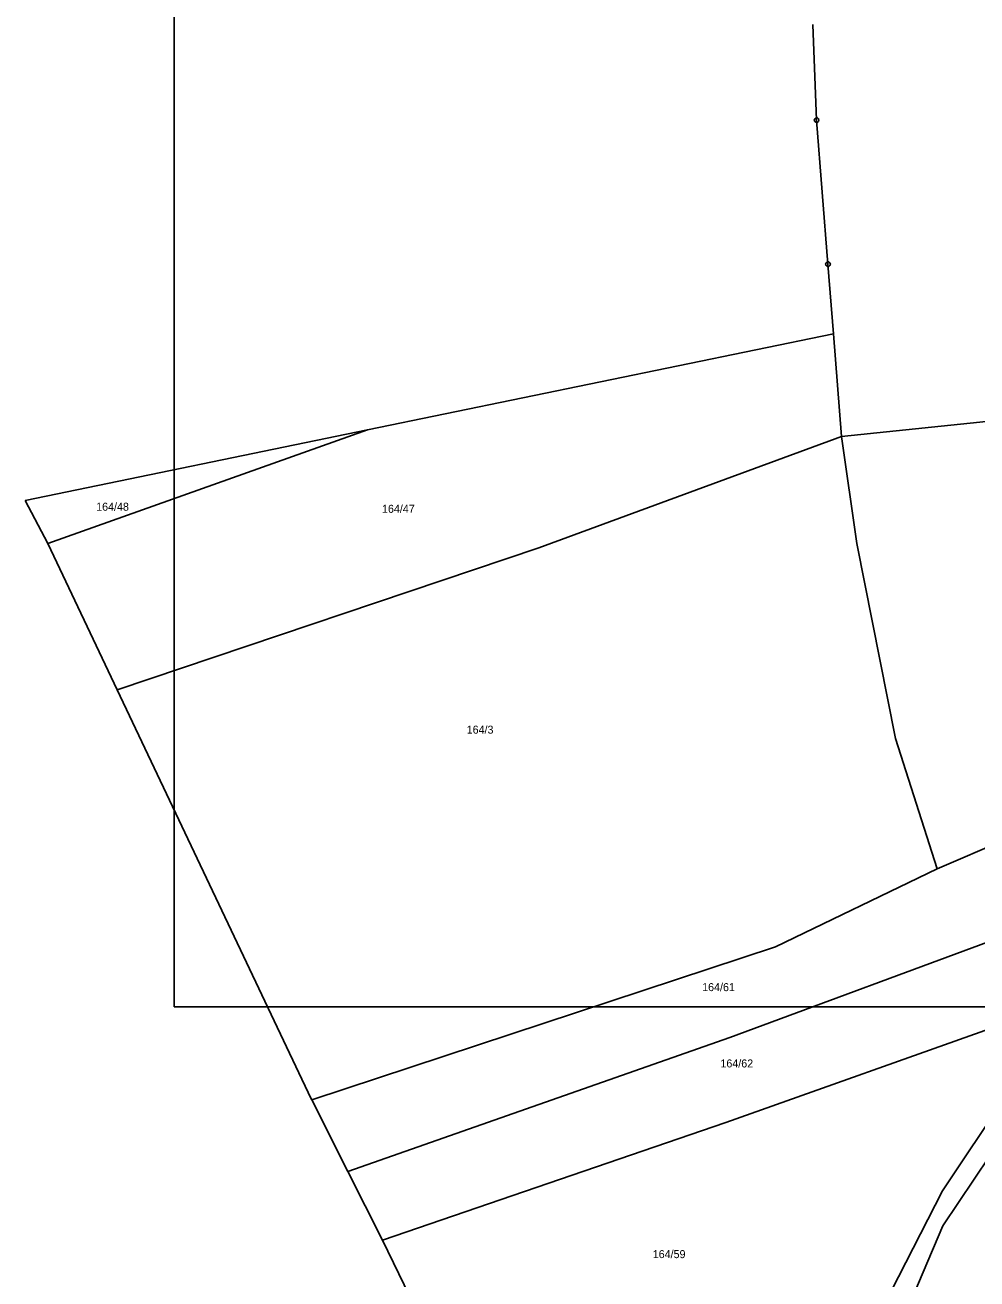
# Model space of a CAD drawing. Extents: x -779723 to -777378, y -1011169 to -1009297.
# Drawn here: x -779562.3 to -779360.2, y -1010745.7 to -1010479.3 of the extents above; entities that cross this region are included whole.
import ezdxf

# ---------------------------------------------------------------- set-up
doc = ezdxf.new("R2010")
doc.units = 0
for name, color, linetype in [('Default', 7, 'Continuous'), ('KN_HRANICE', 7, 'Continuous'), ('KN_PARCELY', 7, 'Continuous'), ('LEGENDA', 7, 'Continuous')]:
    doc.layers.add(name, color=color, linetype=linetype)

# ---------------------------------------------------------------- blocks, each defined once
blk = doc.blocks.new('105')
at = {"layer": 'Default'}
blk.add_line((-0.12, 0), (0.12, 0), dxfattribs=at)
blk.add_lwpolyline([(0.15, 0.48), (0.4, 0.3), (0.5, 0.01), (0.4, -0.28), (0.15, -0.46), (-0.16, -0.46), (-0.41, -0.28), (-0.51, 0.01), (-0.41, 0.3), (-0.16, 0.48), (0.15, 0.48)], dxfattribs=at)

msp = doc.modelspace()

# ---------------------------------------------------------------- linework, layer by layer
at = {"layer": 'KN_HRANICE'}
for p, q in [((-779394.26, -1010499.5), (-779395.1, -1010479.15)), ((-779391.85, -1010530.1), (-779394.26, -1010499.5)), ((-779390.7, -1010544.93), (-779391.85, -1010530.1)), ((-779489.63, -1010565.32), (-779390.7, -1010544.93)), ((-779389.01, -1010566.7), (-779390.7, -1010544.93)), ((-779389.01, -1010566.7), (-779301.63, -1010557.72)), ((-779562.34, -1010580.31), (-779489.63, -1010565.32)), ((-779489.63, -1010565.32), (-779557.53, -1010589.43)), ((-779389.01, -1010566.7), (-779453.28, -1010590.34)), ((-779389.01, -1010566.7), (-779385.7, -1010589.44)), ((-779557.53, -1010589.43), (-779562.34, -1010580.31)), ((-779557.53, -1010589.43), (-779542.79, -1010620.51)), ((-779453.28, -1010590.34), (-779542.79, -1010620.51)), ((-779385.7, -1010589.44), (-779377.52, -1010630.85)), ((-779542.79, -1010620.51), (-779501.57, -1010707.41)), ((-779377.52, -1010630.85), (-779368.68, -1010658.56)), ((-779368.68, -1010658.56), (-779348.77, -1010649.95)), ((-779402.97, -1010675.13), (-779368.68, -1010658.56)), ((-779326.62, -1010662.54), (-779412.71, -1010694.4)), ((-779501.45, -1010707.65), (-779402.97, -1010675.13)), ((-779340.67, -1010686.56), (-779413.52, -1010712.43)), ((-779412.71, -1010694.4), (-779493.79, -1010722.84)), ((-779367.53, -1010726.93), (-779347.72, -1010697.18)), ((-779501.45, -1010707.65), (-779501.57, -1010707.41)), ((-779493.79, -1010722.84), (-779501.45, -1010707.65)), ((-779349.1, -1010706.93), (-779367.48, -1010734.41)), ((-779413.52, -1010712.43), (-779486.45, -1010737.42)), ((-779486.45, -1010737.42), (-779493.79, -1010722.84)), ((-779378.43, -1010748.27), (-779367.53, -1010726.93)), ((-779367.48, -1010734.41), (-779381.29, -1010767)), ((-779465.55, -1010780.39), (-779486.45, -1010737.42))]:
    msp.add_line(p, q, dxfattribs=at)
at = {"layer": 'LEGENDA'}
msp.add_lwpolyline([(-779530.66, -1010687.91), (-778936.66, -1010687.91), (-778936.66, -1010267.91), (-779530.66, -1010267.91)], close=True, dxfattribs=at)

# ---------------------------------------------------------------- block references
at = {"layer": 'KN_PARCELY'}
for p in [(-779394.26, -1010499.5), (-779391.85, -1010530.1)]:
    msp.add_blockref('105', p, dxfattribs=at)

# ---------------------------------------------------------------- texts
for s, p in [('164/48', (-779547.25, -1010582.48)), ('164/47', (-779486.55, -1010582.92)), ('164/3', (-779468.57, -1010629.84)), ('164/61', (-779418.57, -1010684.54)), ('164/62', (-779414.69, -1010700.75)), ('164/59', (-779429.06, -1010741.26))]:
    msp.add_text(s, height=1.7, dxfattribs=at).set_placement(p)

doc.saveas('drawing.dxf')
